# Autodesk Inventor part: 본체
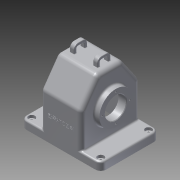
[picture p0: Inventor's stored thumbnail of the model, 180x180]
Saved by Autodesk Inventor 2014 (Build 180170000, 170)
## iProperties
Created: 2016-12
Part Number: 본체
Material: 알루미늄 6061
Document SubType Name: Modeling
Designer: USER
Density: 2.71 g/cm^3
Appearance: 알루미늄 - 평지
Mass: 1130.69 g
Surface Area: 1150.15 cm^2
Volume: 417.231 cm^3
Author: USER
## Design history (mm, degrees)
sketch "스케치1"
  geometry: L1 (75, -55)-(-75, -55); L2 (-75, -55)-(-75, 55); L3 (-75, 55)-(75, 55); L4 (75, 55)-(75, -55); L5 (75, -55)-(-75, 55); L6 (-75, -55)-(75, 55); 1 further point
  constraints: 12 end point, 2 midpoint, 2 parallel, 1 horizontal, 1 perpendicular
  dimensions: "d0" = 110 distance between parallel lines of L1 L3; "d1" = 150 distance between parallel lines of L2 L4
extrude "돌출1" new body sketch "스케치1" distance "d2" = 15; taper "d3" = 0 deg
sketch "스케치2"
  geometry: L1 (-55, 15)-(55, 15); L2 (55, 15)-(55, 80); L3 (55, 80)-(-55, 80); L4 (-55, 80)-(-55, 15); L5 (-55, 0)-(55, 0) reference; L6 (-55, 0)-(-55, 15) reference; L7 (55, 15)-(-55, 15) reference; L8 (55, 0)-(55, 15) reference; L9 (-55, 80)-(-23.491, 125); L10 (-23.491, 125)-(23.491, 125); L11 (23.491, 125)-(55, 80); 1 further point
  constraints: 14 end point, 2 parallel, 2 perpendicular, 1 horizontal
  dimensions: "d4" = 80 distance between parallel lines of L3 L5; "d5" = 35 deg angle of L4 L9; "d6" = 35 deg angle of L2 L11; "d7" = 125 distance from line of point (0, 0) L10
extrude "돌출2" join sketch "스케치2" stored distance "d8" = 77; taper "d9" = 0 deg
node "작업 평면1"
sketch "스케치3"
  geometry: L1 (-12.5, 125)-(12.5, 125); L2 (12.5, 125)-(12.5, 132); L3 (4.5, 140)-(-4.5, 140); L4 (-12.5, 132)-(-12.5, 125); L5 (-23.491, 125)-(23.491, 125) reference; L6 (-55, 0)-(55, 0) reference; A1 r 8 centre (4.5, 132) between (12.5, 132) and (4.5, 140); A2 r 8 centre (-4.5, 132) between (-4.5, 140) and (-12.5, 132); 2 further points
  constraints: 8 end point, 4 point on circle, 4 tangent, 2 centre point, 2 midpoint, 2 parallel, 1 equal radius, 1 horizontal, 1 perpendicular
  dimensions: "d11" = 25 distance between parallel lines of L4 L2; "d12" = 140 distance between parallel lines of L6 L3; "d13" = 8 radius of A1
extrude "돌출3" join sketch "스케치3" distance "d14" = 8; taper "d15" = 0 deg
sketch "스케치4"
  geometry: L1 (-125, 12.5)-(-125, -12.5) reference; L2 (-125, 12.5)-(-132, 12.5) reference; L3 (-140, 4.5)-(-140, -4.5) reference; L4 (-132, -12.5)-(-125, -12.5) reference; L5 (-132, 7.5)-(-130, 7.5); L6 (-130, 7.5)-(-130, -7.5); L7 (-130, -7.5)-(-132, -7.5); L8 (-135, -4.5)-(-135, 4.5); L9 (-130, -7.5)-(-125, -7.5); L10 (-125, -7.5)-(-125, 7.5); L11 (-125, 7.5)-(-130, 7.5); L12 (-130, 7.5)-(-130, -7.5); A1 r 8 centre (-132, 4.5) between (-132, 12.5) and (-140, 4.5) reference; A2 r 8 centre (-132, -4.5) between (-140, -4.5) and (-132, -12.5) reference; A3 r 3 centre (-132, 4.5) between (-132, 7.5) and (-135, 4.5); A4 r 3 centre (-132, -4.5) between (-135, -4.5) and (-132, -7.5); 1 further point
  constraints: 16 end point, 4 point on circle, 2 centre point, 2 parallel, 1 collinear, 1 horizontal, 1 perpendicular, 1 point on line, 5 other
  dimensions: "d16" = 15 distance between parallel lines of L7 L5
extrude "돌출4" cut sketch "스케치4" stored distance "d17" = 8; taper "d18" = 0 deg
sketch "스케치5"
  geometry: L1 (23.491, 125)-(55, 80) reference; L2 (55, 80)-(55, 15) reference; L3 (-55, 15)-(55, 15) reference; L4 (-55, 15)-(-55, 80) reference; L5 (-55, 80)-(-23.491, 125) reference; L6 (-23.491, 125)-(23.491, 125) reference; L7 (-55, 0)-(55, 0) reference; L8 (-55, 0)-(-55, 15) reference; L9 (55, 15)-(-55, 15) reference; L10 (55, 0)-(55, 15) reference; L11 (50, 78.424)-(20.888, 120); L12 (20.888, 120)-(-20.888, 120); L13 (-20.888, 120)-(-50, 78.424); L14 (-50, 78.424)-(-50, 20); L15 (-50, 20)-(50, 20); L16 (50, 20)-(50, 78.424); L17 (-50, 20)-(50, 20); L18 (50, 20)-(50, 0); L19 (50, 0)-(-50, 0); L20 (-50, 0)-(-50, 20); 1 further point
  constraints: 20 end point, 2 parallel, 1 collinear, 1 horizontal, 1 perpendicular, 1 point on line, 5 other
  dimensions: "d19" = 5 distance between parallel lines of L1 L11
extrude "돌출5" cut sketch "스케치5" stored distance "d20" = 67; taper "d21" = 0 deg
sketch "스케치6"
  geometry: L1 (33.5, 111)-(14.5, 92); L2 (14.5, 92)-(14.5, 65); L3 (14.5, 65)-(33.5, 65); L4 (38.5, 80)-(38.5, 15) reference; L5 (-33.5, 0)-(33.5, 0) reference; L6 (33.5, 111)-(33.5, 65); L7 (33.5, 120)-(33.5, 78.424) reference; 1 further point
  constraints: 8 end point, 2 perpendicular, 1 collinear, 1 vertical
  dimensions: "d22" = 54 diameter of L1.end L3; "d23" = 65 distance between parallel lines of L5 L3; "d24" = 45 deg angle of L1 L2; "d94" = 24 distance between parallel lines of L4 L2
revolve "회전1" sketch "스케치6" stored, may be unused: angle "d26" = 90 deg
sketch "스케치7"
  geometry: L1 (0, -55)-(0, 55) reference; C1 r 37.5 at (65, 0); 2 further points
  constraints: 1 centre point, 1 horizontal alignment, 1 midpoint
  dimensions: "d27" = 75 diameter of C1; "d28" = 65 distance from line of L1 C1.centre
extrude "돌출6" join sketch "스케치7" distance "d29" = 5; taper "d30" = 0 deg
sketch "스케치8"
  geometry: L1 (-15, 55)-(-15, -55) reference; L2 (0, 55)-(0, -55) reference; C1 r 31 at (-65, 0); 2 further points
  constraints: 1 centre point, 1 horizontal alignment, 1 midpoint
  dimensions: "d31" = 62 diameter of C1; "d32" = 65 distance from line of L2 C1.centre
extrude "돌출7" join sketch "스케치8" distance "d33" = 10; taper "d34" = 0 deg
hole "구멍1" diameter "d37" = 40; stored, may be unused: countersink angle "d41" = 90 deg, drill point angle "d43" = 118 deg; dims "d35" = 10, "d36" = 10, "d38" = 6, "d39" = 4, "d40" = 2, "d42" = 8
sketch "스케치9"
  geometry: C1 r 20 at (0, 0) reference; 2 further points
  constraints: 1 horizontal alignment
  dimensions: "d44" = 26 distance of C1.centre point (-26, 0)
hole "구멍2" sketch "스케치9" at (-26, 0) diameter "d45" = 2.459; stored, may be unused: countersink angle "d49" = 90 deg, drill point angle "d51" = 118 deg; dims "d46" = 6, "d47" = 4, "d48" = 2, "d50" = 8
sketch "스케치10"
  geometry: C1 r 20 at (0, 0) reference; 2 further points
  constraints: 1 horizontal alignment
  dimensions: "d55" = 29 distance of C1.centre point (29, 0)
hole "구멍3" sketch "스케치10" at (29, 0) diameter "d56" = 2.459; stored, may be unused: countersink angle "d60" = 90 deg, drill point angle "d62" = 118 deg; dims "d57" = 6, "d58" = 4, "d59" = 2, "d61" = 8
fillet "모깎기1" dims "d66" = 10
sketch "스케치11"
  geometry: A1 r 10 centre (-65, 45) between (-65, 55) and (-75, 45) reference; A2 r 10 centre (-65, -45) between (-75, -45) and (-65, -55) reference; 1 further point
hole "구멍4" sketch "스케치11" at (-65, -45), (-65, 45) diameter "d67" = 5; stored, may be unused: countersink angle "d71" = 90 deg, drill point angle "d73" = 118 deg; dims "d68" = 6, "d69" = 12, "d70" = 5, "d72" = 8
fillet "모깎기2" dims "d74" = 10
fillet "모깎기3" dims "d75" = 10
fillet "모깎기4" dims "d76" = 8
fillet "모깎기5" dims "d77" = 3
fillet "모깎기6" dims "d78" = 3
fillet "모깎기7" dims "d79" = 3
fillet "모깎기8" dims "d80" = 1
fillet "모깎기9" dims "d81" = 1
fillet "모깎기10" dims "d82" = 1
fillet "모깎기11" dims "d83" = 1
fillet "모깎기12" dims "d84" = 3
fillet "모깎기13" dims "d85" = 3
fillet "모깎기14" dims "d86" = 3
chamfer "모따기1" distance "d87" = 1; stored, may be unused: second distance "d88" = 2, angle "d89" = 45 deg
sketch "스케치12"
  geometry: L1 (130, 0)-(0, 0) reference; L2 (26.5, 76.847)-(26.5, 18) reference; 2 further points
  constraints: 1 other
  dimensions: "d90" = 38.5 distance from line of L2 point (65, 45); "d91" = 45 distance from line of point (65, 45) L1
feature "엠보싱1" sketch "스케치12" dims "d92" = 0.5, "d93" = 0
node "솔리드1"
mirror "대칭1"
pattern_circular "원형 패턴1" dims angle "d53" = 360 deg
pattern_circular "원형 패턴2" dims angle "d64" = 360 deg
mirror "대칭2"
node "투영된 루프1"
node "투영된 루프2"
node "투영된 루프3"
other parameters: "d10" = 18
